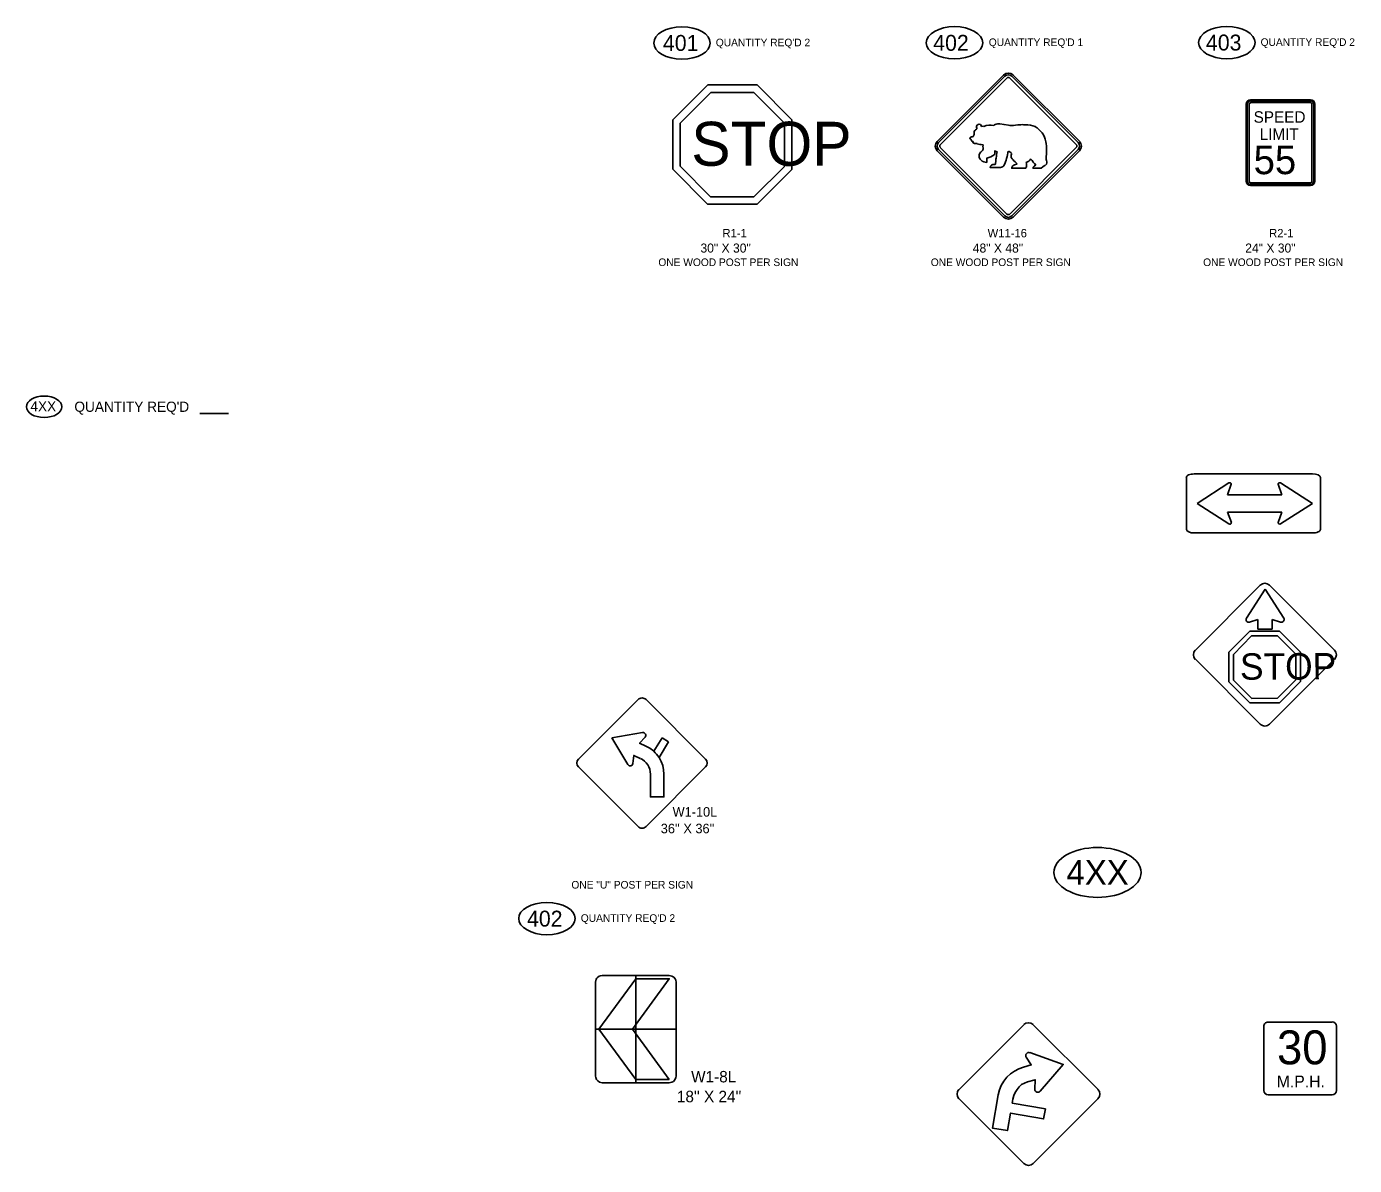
# Model space of a CAD drawing. Extents: x 1977705 to 1981198, y 827296 to 829291.
# Drawn here: x 1978121 to 1979166, y 828239 to 829135 of the extents above; entities that cross this region are included whole.
import ezdxf

# ---------------------------------------------------------------- set-up
doc = ezdxf.new("R2010")
doc.units = 0
for name, color, linetype in [('Default', 7, 'Continuous'), ('Level 11', 7, 'Continuous'), ('Level 24', 7, 'Continuous'), ('Level 34', 7, 'Continuous'), ('Level 37', 7, 'Continuous')]:
    doc.layers.add(name, color=color, linetype=linetype)

msp = doc.modelspace()

# ---------------------------------------------------------------- linework, layer by layer
at = {"layer": 'Default'}
for p, q in [((1978837.5, 829045.1), (1978889.6, 829097.3)), ((1978838.4, 829044.1), (1978890.6, 829096.3)), ((1978892.1, 829094.8), (1978839.9, 829042.6)), ((1978946.8, 829042.7), (1978894.6, 829094.8)), ((1978896.1, 829096.3), (1978948.3, 829044.2)), ((1978897.1, 829097.3), (1978949.3, 829045.2)), ((1978629.4, 829062.1), (1978656.9, 829089.7)), ((1978635.3, 829059.3), (1978659.4, 829083.5)), ((1978656.9, 829089.7), (1978676.4, 829089.6)), ((1978659.4, 829083.5), (1978693.2, 829083.5)), ((1978676.4, 829089.6), (1978695.8, 829089.5)), ((1978693.2, 829083.5), (1978717.3, 829059.3)), ((1978695.8, 829089.5), (1978723.2, 829062)), ((1979080.4, 829074.4), (1979080.5, 829013.7)), ((1979081.3, 829074.4), (1979081.3, 829013.7)), ((1979082.7, 829074.4), (1979082.7, 829013.7)), ((1979131.1, 829077.8), (1979083.8, 829077.8)), ((1979131.1, 829077), (1979083.8, 829077)), ((1979131.1, 829075.6), (1979083.8, 829075.6)), ((1979132.2, 829013.7), (1979132.2, 829074.5)), ((1979133.6, 829013.7), (1979133.6, 829074.5)), ((1979134.5, 829013.7), (1979134.4, 829074.5)), ((1978629.4, 829023.2), (1978629.4, 829062.1)), ((1978723.2, 829062), (1978723.2, 829023.1)), ((1978635.3, 829025.6), (1978635.3, 829059.3)), ((1978717.3, 829059.3), (1978717.3, 829025.4)), ((1978839.9, 829040.1), (1978892.2, 828987.9)), ((1978894.7, 828988), (1978946.8, 829040.2)), ((1978889.7, 828985.5), (1978837.5, 829037.6)), ((1978890.7, 828986.5), (1978838.5, 829038.6)), ((1978871.7, 829036.7), (1978873, 829038)), ((1978948.3, 829038.7), (1978896.2, 828986.5)), ((1978949.3, 829037.7), (1978897.1, 828985.5)), ((1978656.8, 828995.7), (1978629.4, 829023.2)), ((1978659.2, 829001.4), (1978635.3, 829025.6)), ((1978717.3, 829025.4), (1978693.2, 829001.4)), ((1978723.2, 829023.1), (1978695.7, 828995.6)), ((1979083.8, 829012.6), (1979131.1, 829012.6)), ((1979083.8, 829011.2), (1979131.1, 829011.2)), ((1979083.8, 829010.3), (1979131.1, 829010.3)), ((1978693.2, 829001.4), (1978659.2, 829001.4)), ((1978676.2, 828995.6), (1978656.8, 828995.7)), ((1978695.7, 828995.6), (1978676.2, 828995.6)), ((1978279.9, 828830.9), (1978257.4, 828830.9)), ((1979041.8, 828760.2), (1979066.9, 828776.4)), ((1979068.7, 828775.3), (1979065.8, 828767)), ((1979108.6, 828767), (1979105.6, 828775.3)), ((1979107.4, 828776.4), (1979132.5, 828760.2)), ((1979066.9, 828744.1), (1979041.8, 828760.2)), ((1979065.8, 828767), (1979108.6, 828767)), ((1979132.5, 828760.2), (1979107.5, 828744.1)), ((1979108.6, 828753.4), (1979065.8, 828753.4)), ((1979065.8, 828753.4), (1979068.8, 828745.2)), ((1979105.6, 828745.2), (1979108.6, 828753.4)), ((1979086.1, 828737), (1979039.6, 828737)), ((1979132.7, 828737), (1979086.1, 828737)), ((1979040.5, 828644.9), (1979091.5, 828695.9)), ((1979149.8, 828644.9), (1979098.8, 828695.9)), ((1979095.3, 828692.9), (1979080.6, 828669.9)), ((1979095.3, 828692.9), (1979080.6, 828669.9)), ((1979110, 828669.9), (1979095.3, 828692.9)), ((1979110, 828669.9), (1979095.3, 828692.9)), ((1979083.1, 828666.8), (1979089.7, 828668.8)), ((1979083.1, 828666.8), (1979089.7, 828668.8)), ((1979089.7, 828668.8), (1979089.7, 828661.3)), ((1979089.7, 828668.8), (1979089.7, 828661.3)), ((1979100.9, 828668.8), (1979107.5, 828666.8)), ((1979100.9, 828668.8), (1979100.9, 828661.3)), ((1979100.9, 828661.3), (1979100.9, 828668.8)), ((1979100.9, 828668.8), (1979107.5, 828666.8)), ((1979066.8, 828643.2), (1979083.2, 828659.8)), ((1979070.4, 828641.5), (1979084.7, 828656.1)), ((1979083.2, 828659.8), (1979094.9, 828659.8)), ((1979084.7, 828656.1), (1979105, 828656.1)), ((1979089.7, 828661.3), (1979100.9, 828661.3)), ((1979089.7, 828661.3), (1979100.9, 828661.3)), ((1979094.9, 828659.8), (1979106.6, 828659.8)), ((1979105, 828656.1), (1979119.5, 828641.7)), ((1979106.6, 828659.8), (1979123.1, 828643.3)), ((1979066.9, 828619.9), (1979066.8, 828643.2)), ((1979123.1, 828643.3), (1979123.2, 828620)), ((1979091.5, 828586.5), (1979040.5, 828637.6)), ((1979070.4, 828621.3), (1979070.4, 828641.5)), ((1979098.8, 828586.5), (1979149.8, 828637.6)), ((1979119.5, 828641.7), (1979119.6, 828621.4)), ((1979083.4, 828603.4), (1979066.9, 828619.9)), ((1979084.8, 828606.8), (1979070.4, 828621.3)), ((1979119.6, 828621.4), (1979105.2, 828606.9)), ((1979123.2, 828620), (1979106.7, 828603.4)), ((1979095, 828603.4), (1979083.4, 828603.4)), ((1979105.2, 828606.9), (1979084.8, 828606.8)), ((1979106.7, 828603.4), (1979095, 828603.4)), ((1978605.7, 828579.9), (1978581.5, 828575.8)), ((1978581.5, 828575.8), (1978594.1, 828554.7)), ((1978605.7, 828579.9), (1978605.7, 828579.9)), ((1978621, 828575.8), (1978614.5, 828565.2)), ((1978618.7, 828560.3), (1978626.2, 828572.6)), ((1978626.2, 828572.6), (1978621, 828575.8)), ((1978603.8, 828559.7), (1978603.8, 828559.8)), ((1978608.4, 828506), (1978655.2, 828552.9)), ((1978854.6, 828299.1), (1978905.6, 828350.1)), ((1978912.8, 828350.1), (1978963.9, 828299.2)), ((1979151.5, 828348.9), (1979151.5, 828298.3)), ((1978905.6, 828240.9), (1978854.6, 828291.8)), ((1978963.9, 828291.9), (1978912.9, 828240.9))]:
    msp.add_line(p, q, dxfattribs=at)
for points in [[(1978867.5, 829054.1), (1978868.3, 829054.7), (1978868.5, 829055.1), (1978868.7, 829055.4)], [(1978882, 829057.6), (1978882.4, 829058), (1978882.9, 829058.3), (1978883.9, 829058.7), (1978884.9, 829058.9), (1978885.8, 829059), (1978886.7, 829058.9), (1978890, 829058.3), (1978893.4, 829057.9), (1978894.6, 829057.7), (1978895.1, 829057.6), (1978895.3, 829057.5), (1978896, 829057.6), (1978896.3, 829057.6), (1978896.9, 829057.7), (1978897.4, 829057.7), (1978899.1, 829057.8), (1978900.8, 829058), (1978903.3, 829058.2), (1978904.3, 829058.3), (1978905.2, 829058.2), (1978906, 829058.2), (1978906.9, 829058.2)], [(1978881.3, 829026.8), (1978881.5, 829026.8), (1978881.7, 829026.8), (1978882, 829026.8), (1978882.3, 829026.8), (1978882.6, 829026.9), (1978883, 829027), (1978883.3, 829027.3), (1978883.4, 829027.4), (1978883.4, 829027.6), (1978883.5, 829029.5), (1978883.5, 829030.8), (1978883.6, 829030.9), (1978883.6, 829031.1), (1978883.7, 829031.9), (1978884, 829033.4), (1978884.1, 829034.9), (1978884.3, 829035.9), (1978884.5, 829036.9), (1978884.2, 829037), (1978883.9, 829037.1), (1978883.6, 829037.2), (1978883.4, 829037.3), (1978883.3, 829037.3), (1978883, 829037.5), (1978882.8, 829037.7), (1978882.8, 829035.6), (1978882.7, 829035.3), (1978882.6, 829035.1), (1978882.4, 829034.7), (1978882.1, 829034.4), (1978880.9, 829033.8), (1978879.5, 829033), (1978878.1, 829032.4), (1978877.2, 829032.1), (1978876.4, 829031.8), (1978876.4, 829028.5)], [(1978900.2, 829027.5), (1978899.8, 829028), (1978899.3, 829028.4), (1978899, 829028.7), (1978898.7, 829029), (1978897.8, 829029.7), (1978897.2, 829030.5), (1978896.4, 829031.3), (1978895.7, 829032.3)], [(1978887.3, 829024.5), (1978879.1, 829024.5), (1978879.1, 829025), (1978879.3, 829025.3), (1978879.5, 829025.6)], [(1978906.8, 829023.9), (1978896.3, 829023.9), (1978896.1, 829023.9), (1978896.1, 829024), (1978896.1, 829024.1), (1978896.1, 829024.1), (1978896.1, 829024.3), (1978896.2, 829024.5), (1978896.2, 829024.7), (1978896.5, 829025.2)], [(1978922.7, 829026.5), (1978921.6, 829025.8), (1978920.5, 829025.1), (1978919.1, 829024.1), (1978918.6, 829023.9), (1978912.7, 829023.9), (1978912.7, 829024), (1978912.8, 829024.3), (1978912.8, 829024.6), (1978913, 829024.9), (1978913.3, 829025.2), (1978913.5, 829025.4), (1978913.7, 829025.6), (1978914, 829025.9), (1978915, 829026.4)], [(1979033.4, 828739.7), (1979033.4, 828780.7)], [(1979039.5, 828783.4), (1979086.1, 828783.4)], [(1979086.1, 828783.4), (1979132.7, 828783.4)], [(1979138.9, 828780.7), (1979138.9, 828739.7)], [(1978602.2, 828605.9), (1978555.3, 828559.1)], [(1978655.2, 828559.1), (1978608.4, 828605.9)], [(1978608.3, 828569.3), (1978603.3, 828571.6), (1978607.7, 828576.4)], [(1978598.1, 828555.6), (1978598.8, 828562), (1978603.9, 828559.6)], [(1978555.3, 828552.9), (1978602.2, 828506)], [(1978611.9, 828547.2), (1978611.8, 828529.3), (1978622.5, 828529.3), (1978622.5, 828547.2)], [(1979097.6, 828352.2), (1979122.9, 828352.2)], [(1979122.9, 828352.2), (1979148.2, 828352.2)], [(1979094.3, 828298.3), (1979094.3, 828348.8)], [(1978905.3, 828316.7), (1978911.4, 828318.4), (1978907.4, 828324.5)], [(1978910.3, 828328.1), (1978936.6, 828318.9), (1978918.5, 828297.8)], [(1978914.2, 828299.4), (1978914.6, 828306.8), (1978908.4, 828305.1)], [(1978896.5, 828288.3), (1978922.5, 828283.8), (1978921.1, 828276), (1978895.1, 828280.5), (1978892.7, 828266.8), (1978880.9, 828268.8), (1978885.4, 828294.9)], [(1979122.9, 828295), (1979097.7, 828295)], [(1979148.2, 828295), (1979122.9, 828295)]]:
    msp.add_lwpolyline(points, dxfattribs=at)
for centre, radius, start, end in [((1978893.4, 829093.6), 5.27, 45.0308, 135.0308), ((1978893.4, 829093.6), 3.87, 45.0308, 135.0308), ((1978893.4, 829093.6), 1.76, 45.0308, 135.0308), ((1979083.8, 829074.4), 3.38, 90.0308, 180.0308), ((1979083.8, 829074.4), 2.53, 90.0308, 180.0308), ((1979083.8, 829074.4), 1.13, 90.0308, 180.0308), ((1979131.1, 829074.5), 3.38, 0.0308, 90.0308), ((1979131.1, 829074.5), 2.53, 0.0308, 90.0308), ((1979131.1, 829074.5), 1.12, 0.0308, 90.0308), ((1978868.7, 829047.8), 3.26, 135.9123, 158.7334), ((1978865.3, 829051), 1.32, 317.4241, 6.7956), ((1978869.4, 829052), 2.9, 131.1137, 196.3519), ((1978870.3, 829056.6), 1.97, 111.9094, 215.4185), ((1978870.4, 829056.8), 1.83, 359.3844, 117.906), ((1978873.2, 829053.8), 3.15, 71.8811, 108.0343), ((1978879.2, 829046.3), 11.6, 76.1817, 115.6445), ((1978906.9, 829038), 20.2, 68.2551, 90.0302), ((1978906.3, 829042), 16.8, 9.7893, 61.4641), ((1978841.2, 829041.4), 5.27, 135.0308, 225.0308), ((1978841.2, 829041.4), 3.87, 135.0308, 225.0308), ((1978841.2, 829041.4), 1.76, 135.0308, 225.0308), ((1978864.1, 829047.6), 0.95, 83.0069, 249.6524), ((1978863.5, 829045.9), 0.9, 359.6212, 69.6524), ((1978864.4, 829050.4), 1.8, 263.0069, 311.0613), ((1978865.3, 829045.9), 0.901, 179.6212, 290.6544), ((1978866.4, 829044.8), 0.82, 162.9609, 188.6765), ((1978867.1, 829044.9), 1.58, 188.6765, 280.7439), ((1978867.9, 829040.8), 2.66, 71.3328, 100.7439), ((1978873.4, 829057), 14.5, 251.4124, 269.4705), ((1978871.5, 829039.5), 2.14, 313.7838, 15.9348), ((1978873.3, 829042.3), 0.225, 347.7257, 89.4705), ((1978877.8, 829041.3), 4.43, 167.7257, 195.9328), ((1978882.4, 829037.9), 41.1, 351.1888, 9.7893), ((1978945.6, 829041.4), 1.76, 315.0308, 45.0308), ((1978945.6, 829041.4), 3.87, 315.0308, 45.0308), ((1978945.6, 829041.4), 5.27, 315.0308, 45.0308), ((1978874.6, 829033.7), 4.23, 133.7838, 230.975), ((1978876.7, 829035.3), 6.81, 225.8476, 267.3554), ((1978855.3, 829042.9), 38.4, 334.241, 351.8593), ((1978885.5, 829022.9), 16.6, 50.8038, 61.5938), ((1978900.6, 829033.4), 5.04, 161.5343, 193.2143), ((1978894.6, 829035.5), 1.31, 336.9242, 7.8812), ((1978902.8, 829038.2), 10.8, 295.3355, 319.9936), ((1978948.9, 829058.5), 46.6, 215.8236, 223.5145), ((1978920.9, 829028.6), 2.79, 311.761, 29.4366), ((1978925.6, 829031.2), 2.59, 171.1888, 207.515), ((1978881.4, 829024.6), 2.19, 92.8189, 153.8066), ((1978887.3, 829027.5), 2.93, 270.0304, 334.241), ((1978898.2, 829024.4), 1.93, 128.6731, 155.9431), ((1978902.1, 829018.7), 8.81, 105.6807, 125.1536), ((1978898.9, 829029.5), 2.47, 289.9342, 303.2012), ((1978906.5, 829024.8), 1.03, 288.9364, 336.0454), ((1978902, 829026.4), 5.78, 340.2812, 20.9865), ((1979083.8, 829013.7), 3.38, 180.0308, 270.0308), ((1979083.8, 829013.7), 2.53, 180.0308, 270.0308), ((1979083.8, 829013.7), 1.12, 180.0308, 270.0308), ((1979131.1, 829013.7), 3.38, 270.0308, 0.0308), ((1979131.1, 829013.7), 2.53, 270.0308, 0.0308), ((1979131.1, 829013.7), 1.12, 270.0308, 0.0308), ((1978893.4, 828989.2), 1.76, 225.0308, 315.0308), ((1978893.4, 828989.2), 5.27, 225.0308, 315.0308), ((1978893.4, 828989.2), 3.87, 225.0308, 315.0308), ((1979095.1, 828692.3), 5.16, 45.0178, 135.0178), ((1979082.4, 828668.8), 2.09, 147.4424, 289.8626), ((1979082.4, 828668.8), 2.09, 147.4424, 289.8626), ((1979108.2, 828668.8), 2.09, 250.1989, 32.6191), ((1979108.2, 828668.8), 2.09, 250.1989, 32.6191), ((1979044.1, 828641.2), 5.16, 135.0178, 225.0178), ((1979146.2, 828641.2), 5.16, 315.0178, 45.0178), ((1978605.3, 828602.8), 4.38, 89.9935, 135), ((1978605.3, 828602.8), 4.38, 44.987, 89.9935), ((1978606.1, 828577.8), 2.12, 317.4787, 99.6007), ((1979095.2, 828590.2), 5.16, 225.0178, 315.0178), ((1978598.2, 828547.2), 13.7, 359.9695, 65.2765), ((1978598.2, 828547.2), 24.3, 359.9695, 65.2765), ((1978598.2, 828547.2), 24.3, 32.623, 47.7498), ((1978558.4, 828556), 4.38, 135, 225), ((1978595.9, 828555.8), 2.12, 210.9523, 353.0808), ((1978652.1, 828556), 4.38, 315, 45), ((1978605.3, 828509.1), 4.38, 225, 270), ((1978605.3, 828509.1), 4.38, 270, 315), ((1978909.2, 828346.5), 5.15, 45.0308, 135.0308), ((1979097.6, 828348.8), 3.34, 90.0178, 180.0308), ((1979148.2, 828348.9), 3.34, 0.0308, 90.0308), ((1978909.5, 828325.8), 2.4, 70.8302, 212.9667), ((1978912.5, 828290.2), 27.5, 105.1539, 170.2164), ((1978858.2, 828295.5), 5.15, 135.0308, 225.0308), ((1978916.6, 828299.3), 2.4, 177.3411, 319.4776), ((1978960.2, 828295.5), 5.15, 315.0308, 45.0308), ((1979097.7, 828298.3), 3.34, 180.0308, 270.0308), ((1979148.2, 828298.3), 3.34, 270.0308, 0.0308), ((1978909.3, 828244.5), 5.15, 225.0308, 315.0308)]:
    msp.add_arc(centre, radius, start, end, dxfattribs=at)
msp.add_ellipse((1978135, 828836.3), major_axis=(-13.9, 0), ratio=0.608767, dxfattribs=at)
for centre, major_axis, ratio, start_param, end_param in [((1979039.5, 828780.7), (-6.15, 0), 0.44, 4.712162, 6.283185), ((1979132.7, 828780.7), (6.15, 0), 0.44, 0, 1.570796), ((1979067.6, 828775.5), (1.17, 0), 0.88, 6.063803, 8.48391), ((1979106.7, 828775.5), (-1.17, 0), 0.88, 4.082461, 6.502568), ((1979039.6, 828739.7), (-6.15, 0), 0.44, 0, 1.570796), ((1979067.6, 828744.9), (1.17, 0), 0.88, 4.082461, 6.502568), ((1979106.8, 828745), (-1.17, 0), 0.88, 6.063803, 8.48391), ((1979132.7, 828739.7), (-6.15, 0), 0.44, 1.570796, 3.141593), ((1978914.3, 828283.3), (-5.9, 21.8), 0.77631, 0, 1.135555)]:
    msp.add_ellipse(centre, major_axis=major_axis, ratio=ratio, start_param=start_param, end_param=end_param, dxfattribs=at)
at = {"layer": 'Level 11'}
for centre in [(1978636.7, 829122.5), (1978851, 829122.7), (1979065.2, 829122.8), (1978530.5, 828433.6)]:
    msp.add_ellipse(centre, major_axis=(-22.2, 0), ratio=0.571429, dxfattribs=at)
at = {"layer": 'Level 24'}
msp.add_line((1978597.7, 828346.6), (1978597.7, 828346.6), dxfattribs=at)
msp.add_lwpolyline([(1978632, 828309.7), (1978632, 828383.5), (1978631.8, 828385.2), (1978631.3, 828386.2), (1978630.3, 828387.4), (1978628.6, 828388.4), (1978626.7, 828388.8), (1978574, 828388.8), (1978572.5, 828388.6), (1978571.5, 828388.2), (1978570.6, 828387.6), (1978569.8, 828386.7), (1978569.2, 828385.8), (1978568.7, 828383.5), (1978568.7, 828309.7), (1978568.8, 828308.5), (1978569.4, 828307), (1978570.4, 828305.8), (1978571.7, 828304.9), (1978574, 828304.4), (1978626.7, 828304.4), (1978628.8, 828304.8), (1978630, 828305.5), (1978631.1, 828306.7), (1978631.8, 828308.5), (1978632, 828309.7)], dxfattribs=at)
msp.add_lwpolyline([(1978626.7, 828307), (1978597.7, 828346.6), (1978626.7, 828386.2), (1978600.4, 828386.2), (1978571.3, 828346.6), (1978600.4, 828307)], close=True, dxfattribs=at)
at = {"layer": 'Level 34'}
for p, q in [((1978600.4, 828388.8), (1978600.4, 828304.4)), ((1978568.7, 828346.6), (1978632, 828346.6))]:
    msp.add_line(p, q, dxfattribs=at)
at = {"layer": 'Level 37'}
msp.add_ellipse((1978963.5, 828469.9), major_axis=(-34.3, 0), ratio=0.571429, dxfattribs=at)

# ---------------------------------------------------------------- texts
at = {"layer": 'Default'}
for s, height, p in [("QUANTITY REQ'D 2", 6, (1978663.3, 829119.9)), ("QUANTITY REQ'D 1", 6, (1978878, 829120.1)), ("QUANTITY REQ'D 2", 6, (1979091.8, 829120.2)), ('STOP', 34.63, (1978644, 829025.9)), ('R1-1', 6.6, (1978668.5, 828969.6)), ('W11-16', 6.6, (1978877.1, 828969.6)), ('R2-1', 6.6, (1979098.5, 828969.6)), ('30" X 30"', 7.12, (1978651.2, 828957.6)), ('48" X 48"', 7.12, (1978865.4, 828957.6)), ('24" X 30"', 7.12, (1979079.7, 828957.6)), ('ONE WOOD POST PER SIGN', 6, (1978618.1, 828947)), ('ONE WOOD POST PER SIGN', 6, (1978832.4, 828947)), ('ONE WOOD POST PER SIGN', 6, (1979046.6, 828947)), ('4XX', 8.02, (1978124.2, 828832.6)), ("QUANTITY REQ'D ", 8.023, (1978158.8, 828832.3)), ('W1-10L', 7.5, (1978629.3, 828513.8)), ("36'' X 36''", 7.5, (1978620, 828500.7)), ('ONE "U" POST PER SIGN', 6, (1978549.7, 828457.2)), ("QUANTITY REQ'D 2", 6, (1978557.1, 828431))]:
    msp.add_text(s, height=height, dxfattribs=at).set_placement(p)
for s, height, rotation, p in [('SPEED', 9, 0.0308, (1979086.3, 829059.8)), ('LIMIT', 9, 0.0308, (1979091, 829046.3)), ('55', 22.5, 0.0308, (1979086.3, 829019.3)), ('STOP', 20.78, 0.2033, (1979075.6, 828621.5)), ('30', 26.7, 0.0308, (1979104.7, 828318.9)), ('W1-8L', 9, 360, (1978643.9, 828304.7)), ('M.P.H.', 9.27, 0.0308, (1979104.5, 828300.8)), ("18'' X 24''", 9, 360, (1978632.7, 828289.1))]:
    msp.add_text(s, height=height, rotation=rotation, dxfattribs=at).set_placement(p)
at = {"layer": 'Level 11'}
for s, p in [('401', (1978621.7, 829116.3)), ('402', (1978834.3, 829116.4)), ('403', (1979048.8, 829116.6)), ('402', (1978514.8, 828427.3))]:
    msp.add_text(s, height=12.52, rotation=359.9659, dxfattribs=at).set_placement(p)
at = {"layer": 'Level 37'}
msp.add_text('4XX', height=19.37, rotation=359.9968, dxfattribs=at).set_placement((1978939.1, 828460.2))

doc.saveas('drawing.dxf')
